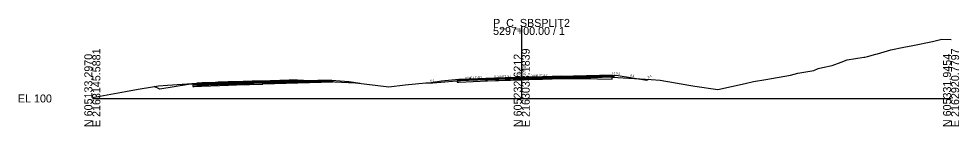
# Model space of a CAD drawing. Extents: x -26 to 1303, y -10 to 12033.
# Drawn here: x -25.7 to 302.8, y 8990.3 to 9027.8 of the extents above; entities that cross this region are included whole.
import ezdxf

# ---------------------------------------------------------------- set-up
doc = ezdxf.new("R2010")
doc.units = 0
for name, color, linetype in [('RD_GPK_XS_Cell', 7, 'Continuous'), ('RD_XS_Base', 7, 'Continuous'), ('RD_XS_ExGround', 7, 'Continuous'), ('RD_XS_ExPaveRet', 7, 'Continuous'), ('RD_XS_Greenside', 7, 'Continuous'), ('RD_XS_Pave', 7, 'Continuous'), ('RD_XS_PaveOvlay_CP', 7, 'Continuous'), ('RD_XS_TieSlope', 7, 'Continuous'), ('RD_XS_TX_Elev_EX', 7, 'Continuous'), ('RD_XS_TX_Elev_PR', 7, 'Continuous'), ('RD_XS_TX_ShdSlope', 7, 'Continuous'), ('RD_XS_TX_Slope', 7, 'Continuous')]:
    doc.layers.add(name, color=color, linetype=linetype)

msp = doc.modelspace()

# ---------------------------------------------------------------- linework, layer by layer
at = {"layer": 'RD_GPK_XS_Cell'}
for p, q in [((150, 9000), (150, 9025)), ((0, 9000), (150, 9000)), ((150, 9000), (300, 9000))]:
    msp.add_line(p, q, dxfattribs=at)
at = {"layer": 'RD_XS_Base'}
for p, q in [((47.57, 9005.2), (38.18, 9004.82)), ((50.32, 9005.27), (47.57, 9005.2)), ((59.57, 9005.51), (50.32, 9005.27)), ((59.57, 9005.51), (84.07, 9006.14)), ((59.57, 9005.01), (59.57, 9005.67)), ((59.57, 9005.67), (59.57, 9005.67)), ((59.57, 9005.67), (59.57, 9005.67)), ((59.57, 9005.67), (59.57, 9005.51)), ((84.07, 9005.64), (59.57, 9005.01)), ((59.57, 9005.51), (59.57, 9005.51)), ((59.57, 9005.01), (59.57, 9005.51)), ((59.57, 9005.51), (59.57, 9005.51)), ((59.57, 9005.51), (59.57, 9005.51)), ((83.57, 9006.13), (83.57, 9006.13)), ((83.57, 9006.13), (83.57, 9006.13)), ((83.57, 9006.13), (83.57, 9006.13)), ((83.57, 9005.63), (83.57, 9005.63)), ((83.57, 9005.63), (83.57, 9005.63)), ((84.07, 9006.14), (84.07, 9005.64)), ((84.07, 9006.11), (84.07, 9006.11)), ((128, 9006.25), (127.5, 9006.23)), ((127.5, 9006.23), (127.5, 9006.23)), ((127.5, 9006.23), (127.5, 9005.73)), ((127.5, 9005.73), (128, 9005.75)), ((138, 9006.65), (128, 9006.25)), ((128, 9006.25), (128, 9006.25)), ((128, 9005.75), (138, 9006.15)), ((128, 9005.75), (128, 9005.75)), ((136, 9006.57), (136, 9006.57)), ((136, 9006.07), (136, 9006.07)), ((150, 9006.99), (138, 9006.65)), ((138, 9006.15), (150, 9006.49)), ((150, 9006.99), (181.7, 9007.88)), ((182.2, 9007.39), (150, 9006.49)), ((150, 9006.49), (150, 9007.15)), ((150, 9007.15), (150, 9007.15)), ((150, 9007.15), (150, 9007.15)), ((150, 9007.15), (150, 9006.99)), ((150, 9006.99), (150, 9006.99)), ((150, 9006.49), (150, 9006.99)), ((150, 9006.99), (150, 9006.99)), ((150, 9006.99), (150, 9006.99)), ((150, 9006.49), (150, 9006.49)), ((162, 9007.33), (162, 9007.33)), ((162, 9007.33), (162, 9007.33)), ((162, 9006.83), (162, 9006.83)), ((162, 9006.83), (162, 9006.83)), ((181.7, 9007.88), (181.7, 9007.88)), ((182.2, 9007.89), (182.2, 9007.39)), ((182.2, 9007.86), (182.2, 9007.86)), ((35.17, 9004.7), (35.06, 9004.7)), ((35.06, 9004.7), (35.06, 9004.3)), ((35.06, 9004.3), (35.06, 9004.2)), ((35.06, 9004.2), (35.17, 9004.2)), ((35.56, 9004.72), (35.17, 9004.7)), ((35.17, 9004.2), (35.56, 9004.22)), ((38.18, 9004.82), (35.56, 9004.72)), ((35.56, 9004.22), (38.18, 9004.32)), ((38.18, 9004.32), (47.57, 9004.7)), ((47.57, 9004.7), (50.32, 9004.77)), ((50.32, 9004.77), (59.57, 9005.01)), ((59.57, 9005.01), (59.57, 9005.01))]:
    msp.add_line(p, q, dxfattribs=at)
at = {"layer": 'RD_XS_ExGround'}
msp.add_lwpolyline([(0, 9000.36), (8.97, 9002.02), (11.57, 9002.4), (15.95, 9003.2), (21.02, 9004.11), (23.12, 9004.47), (26.23, 9004.68), (36.51, 9005.35), (42.99, 9005.63), (44.96, 9005.69), (52.73, 9005.91), (55.29, 9005.98), (56.4, 9006.04), (68.75, 9006.37), (70.77, 9006.42), (71.71, 9006.45), (73.79, 9006.35), (74.65, 9006.3), (91.97, 9005.49), (94.99, 9005.14), (103.59, 9004.12), (109.3, 9004.72), (116.51, 9005.44), (116.93, 9005.45), (118.98, 9005.5), (130.01, 9006.34), (137.5, 9006.97), (144.26, 9007.18), (149.82, 9007.36), (151.67, 9007.42), (153.08, 9007.45), (155, 9007.49), (155.13, 9007.5), (157.28, 9007.55), (163.97, 9007.75), (171.13, 9007.67), (176.53, 9007.59), (181.57, 9007.48), (195.21, 9006.64), (198.35, 9006.45), (208.4, 9004.65), (209.09, 9004.53), (210.45, 9004.33), (218.53, 9003.1), (228.1, 9005.25), (230.98, 9005.94), (235.27, 9006.57), (243.85, 9008.16), (245.14, 9008.48), (246.47, 9008.79), (252.02, 9009.8), (253.62, 9010.46), (255.13, 9010.85), (258.48, 9011.54), (261.66, 9012.73), (263.65, 9013.51), (269.58, 9014.41), (269.75, 9014.42), (269.88, 9014.47), (270.83, 9014.71), (273.77, 9015.48), (274.26, 9015.63), (278.94, 9016.95), (283.51, 9017.96), (286.69, 9018.49), (293.54, 9019.87), (296.82, 9020.67), (300, 9020.62)], dxfattribs=at)
at = {"layer": 'RD_XS_ExPaveRet'}
for points in [[(70.77, 9006.42), (68.75, 9006.37), (62.08, 9006.19), (56.4, 9006.04), (55.85, 9006.01), (55.29, 9005.98), (54.01, 9005.95), (52.73, 9005.91), (47.42, 9005.76), (44.96, 9005.69), (43.98, 9005.66), (42.99, 9005.63), (38.38, 9005.43), (36.51, 9005.35), (36.51, 9005.35), (36.51, 9005.35), (36.51, 9004.84), (36.51, 9004.6), (36.51, 9004.6), (36.51, 9004.6), (38.38, 9004.68), (42.99, 9004.88), (43.98, 9004.91), (44.96, 9004.94), (47.42, 9005.01), (52.73, 9005.16), (54.01, 9005.2), (55.29, 9005.23), (55.85, 9005.26), (56.4, 9005.29), (62.08, 9005.44), (68.75, 9005.62), (70.77, 9005.67), (71.71, 9005.7), (71.71, 9006.04), (71.71, 9006.45), (70.77, 9006.42)], [(70.77, 9006.42), (68.75, 9006.37), (62.08, 9006.19), (56.4, 9006.04), (55.85, 9006.01), (55.29, 9005.98), (54.01, 9005.95), (52.73, 9005.91), (47.42, 9005.76), (44.96, 9005.69), (43.98, 9005.66), (42.99, 9005.63), (38.38, 9005.43), (36.51, 9005.35), (36.51, 9005.35), (36.51, 9004.84), (36.51, 9004.6), (36.51, 9004.6), (38.38, 9004.68), (42.99, 9004.88), (43.98, 9004.91), (44.96, 9004.94), (47.42, 9005.01), (52.73, 9005.16), (54.01, 9005.2), (55.29, 9005.23), (55.85, 9005.26), (56.4, 9005.29), (62.08, 9005.44), (68.75, 9005.62), (70.77, 9005.67), (71.71, 9005.7), (71.71, 9006.04), (71.71, 9006.45), (70.77, 9006.42)], [(181.57, 9007.48), (176.53, 9007.59), (171.13, 9007.67), (171.13, 9007.67), (163.97, 9007.75), (157.28, 9007.55), (157.28, 9007.55), (157.28, 9007.55), (155.13, 9007.5), (155, 9007.49), (153.08, 9007.45), (153.08, 9007.45), (153.08, 9007.45), (151.67, 9007.42), (151.67, 9007.42), (149.82, 9007.36), (149.82, 9007.36), (149.82, 9007.36), (144.26, 9007.18), (144.26, 9007.18), (137.5, 9006.97), (137.5, 9006.97), (137.5, 9006.97), (137.5, 9006.22), (137.5, 9006.22), (144.26, 9006.43), (144.26, 9006.43), (149.82, 9006.61), (149.82, 9006.61), (149.82, 9006.61), (151.67, 9006.67), (151.67, 9006.67), (153.08, 9006.7), (153.08, 9006.7), (153.08, 9006.7), (155, 9006.74), (155.13, 9006.75), (157.28, 9006.8), (157.28, 9006.8), (157.28, 9006.8), (163.97, 9007), (171.13, 9006.92), (171.13, 9006.92), (176.53, 9006.84), (181.57, 9006.73), (181.57, 9006.73), (181.57, 9006.73), (181.57, 9007.48), (181.57, 9007.48), (181.57, 9007.48), (181.57, 9007.48)], [(181.57, 9007.48), (176.53, 9007.59), (171.13, 9007.67), (163.97, 9007.75), (157.28, 9007.55), (155.13, 9007.5), (155, 9007.49), (153.08, 9007.45), (151.67, 9007.42), (149.82, 9007.36), (144.26, 9007.18), (137.5, 9006.97), (137.5, 9006.97), (137.5, 9006.22), (137.5, 9006.22), (144.26, 9006.43), (149.82, 9006.61), (151.67, 9006.67), (153.08, 9006.7), (155, 9006.74), (155.13, 9006.75), (157.28, 9006.8), (163.97, 9007), (171.13, 9006.92), (176.53, 9006.84), (181.57, 9006.73), (181.57, 9007.48)]]:
    msp.add_lwpolyline(points, dxfattribs=at)
at = {"layer": 'RD_XS_Greenside'}
for p, q in [((89.57, 9005.97), (93.53, 9005.31)), ((122, 9006.09), (118.36, 9005.48)), ((183.7, 9008.04), (193.7, 9006.37)), ((193.7, 9006.37), (194.36, 9006.69)), ((23.56, 9003.21), (21.6, 9004.19)), ((33.56, 9004.87), (23.56, 9003.21))]:
    msp.add_line(p, q, dxfattribs=at)
at = {"layer": 'RD_XS_Pave'}
for p, q in [((38.18, 9005.14), (35.56, 9005.03)), ((47.57, 9005.51), (38.18, 9005.14)), ((38.18, 9004.98), (47.57, 9005.36)), ((47.57, 9005.36), (38.18, 9004.98)), ((38.18, 9004.82), (47.57, 9005.2)), ((50.32, 9005.59), (47.57, 9005.51)), ((47.57, 9005.36), (50.32, 9005.43)), ((50.32, 9005.43), (47.57, 9005.36)), ((47.57, 9005.2), (50.32, 9005.27)), ((59.57, 9005.83), (50.32, 9005.59)), ((50.32, 9005.43), (59.57, 9005.67)), ((59.57, 9005.67), (50.32, 9005.43)), ((50.32, 9005.27), (59.57, 9005.51)), ((83.57, 9006.45), (59.57, 9005.83)), ((83.57, 9006.29), (59.57, 9005.67)), ((59.57, 9005.67), (83.57, 9006.29)), ((59.57, 9005.51), (83.57, 9006.13)), ((59.57, 9005.83), (59.57, 9005.83)), ((59.57, 9005.67), (59.57, 9005.67)), ((59.57, 9005.67), (59.57, 9005.67)), ((59.57, 9005.67), (59.57, 9005.51)), ((59.57, 9005.67), (59.57, 9005.67)), ((59.57, 9005.51), (59.57, 9005.67)), ((59.57, 9005.67), (59.57, 9005.67)), ((59.57, 9005.67), (59.57, 9005.67)), ((59.57, 9005.51), (59.57, 9005.51)), ((59.57, 9005.51), (59.57, 9005.51)), ((83.57, 9006.29), (83.57, 9006.45)), ((83.57, 9006.45), (83.57, 9006.45)), ((83.57, 9006.45), (83.57, 9006.45)), ((83.57, 9006.45), (83.57, 9006.45)), ((83.57, 9006.13), (83.57, 9006.29)), ((83.57, 9006.29), (83.57, 9006.29)), ((83.57, 9006.29), (83.57, 9006.29)), ((83.57, 9006.29), (83.57, 9006.29)), ((83.57, 9006.29), (83.57, 9006.29)), ((83.57, 9006.29), (83.57, 9006.29)), ((83.57, 9006.13), (83.57, 9006.13)), ((83.57, 9006.13), (83.57, 9006.13)), ((138, 9006.97), (128, 9006.57)), ((128, 9006.41), (138, 9006.81)), ((138, 9006.81), (128, 9006.41)), ((128, 9006.25), (138, 9006.65)), ((128, 9006.57), (128, 9006.57)), ((128, 9006.57), (128, 9006.41)), ((128, 9006.41), (128, 9006.41)), ((128, 9006.41), (128, 9006.25)), ((136, 9006.89), (136, 9006.89)), ((136, 9006.73), (136, 9006.73)), ((136, 9006.73), (136, 9006.73)), ((136, 9006.57), (136, 9006.57)), ((150, 9007.31), (138, 9006.97)), ((138, 9006.81), (150, 9007.15)), ((150, 9007.15), (138, 9006.81)), ((138, 9006.65), (150, 9006.99)), ((181.7, 9008.2), (150, 9007.31)), ((181.7, 9008.04), (150, 9007.15)), ((150, 9007.15), (181.7, 9008.04)), ((150, 9006.99), (182.2, 9007.89)), ((150, 9007.31), (150, 9007.31)), ((150, 9007.15), (150, 9007.15)), ((150, 9007.15), (150, 9007.15)), ((150, 9007.15), (150, 9006.99)), ((150, 9007.15), (150, 9007.15)), ((150, 9006.99), (150, 9007.15)), ((150, 9007.15), (150, 9007.15)), ((150, 9007.15), (150, 9007.15)), ((150, 9006.99), (150, 9006.99)), ((150, 9006.99), (150, 9006.99)), ((162, 9007.64), (162, 9007.64)), ((162, 9007.64), (162, 9007.64)), ((162, 9007.49), (162, 9007.49)), ((162, 9007.49), (162, 9007.49)), ((162, 9007.49), (162, 9007.49)), ((162, 9007.49), (162, 9007.49)), ((162, 9007.33), (162, 9007.33)), ((162, 9007.33), (162, 9007.33)), ((181.7, 9008.04), (181.7, 9008.2)), ((181.7, 9008.2), (181.7, 9008.2)), ((181.7, 9007.88), (181.7, 9008.04)), ((181.7, 9008.04), (181.7, 9008.04)), ((35.56, 9005.03), (35.56, 9004.91)), ((35.56, 9004.88), (38.18, 9004.98)), ((38.18, 9004.98), (35.56, 9004.88)), ((35.56, 9004.91), (35.56, 9004.88)), ((35.56, 9004.88), (35.56, 9004.75)), ((35.56, 9004.72), (38.18, 9004.82)), ((35.56, 9004.75), (35.56, 9004.72))]:
    msp.add_line(p, q, dxfattribs=at)
at = {"layer": 'RD_XS_PaveOvlay_CP'}
for p, q in [((38.18, 9005.14), (35.56, 9005.03)), ((47.57, 9005.51), (38.18, 9005.14)), ((50.32, 9005.59), (47.57, 9005.51)), ((59.57, 9005.83), (50.32, 9005.59)), ((83.57, 9006.45), (59.57, 9005.83)), ((59.57, 9005.83), (59.57, 9005.83)), ((83.57, 9006.45), (83.57, 9006.45)), ((83.57, 9006.45), (83.57, 9006.45)), ((138, 9006.97), (128, 9006.57)), ((136, 9006.89), (136, 9006.89)), ((150, 9007.31), (138, 9006.97)), ((181.7, 9008.2), (150, 9007.31)), ((150, 9007.31), (150, 9007.31)), ((162, 9007.64), (162, 9007.64)), ((162, 9007.64), (162, 9007.64))]:
    msp.add_line(p, q, dxfattribs=at)
at = {"layer": 'RD_XS_TieSlope'}
for p, q in [((83.57, 9006.45), (89.57, 9005.97)), ((128, 9006.57), (122, 9006.09)), ((181.7, 9008.2), (183.7, 9008.04)), ((35.56, 9005.03), (33.56, 9004.87))]:
    msp.add_line(p, q, dxfattribs=at)

# ---------------------------------------------------------------- texts
at = {"layer": 'RD_GPK_XS_Cell'}
for s, p in [('5297+00.00 / 1', (140, 9022.2)), ('P_C_SBSPLIT2', (140, 9025)), ('EL 100', (-26, 8998.6))]:
    msp.add_text(s, height=2.8, dxfattribs=at).set_placement(p)
for s, p in [('N 605133.2970', (0, 8990)), ('E 2163145.5881', (2.8, 8990)), ('N 605232.6212', (150, 8990)), ('E 2163033.1839', (152.8, 8990)), ('N 605331.9454', (300, 8990)), ('E 2162920.7797', (302.8, 8990))]:
    msp.add_text(s, height=2.8, rotation=90, dxfattribs=at).set_placement(p)
at = {"layer": 'RD_XS_TX_Elev_EX'}
msp.add_text('107.36', height=0.6, rotation=90, dxfattribs=at).set_placement((149.49, 9008.28))
at = {"layer": 'RD_XS_TX_Elev_PR'}
msp.add_text('107.31', height=1, rotation=90, dxfattribs=at).set_placement((151.33, 9007.85))
at = {"layer": 'RD_XS_TX_ShdSlope'}
msp.add_text('12.5:1', height=0.75, rotation=355.4261, dxfattribs=at).set_placement((181.5, 9008.53))
at = {"layer": 'RD_XS_TX_Slope'}
for s, rotation, p in [('0.030 FT./FT.', 1.7184, (153.16, 9007.57)), ('6:1', 350.5358, (187.84, 9007.72)), ('6:1', 9.4623, (118.12, 9005.75)), ('0.040 FT./FT.', 2.2906, (130.15, 9006.78)), ('0.030 FT./FT.', 1.7184, (140.42, 9007.21)), ('2:1', 26.5651, (194.22, 9007.04))]:
    msp.add_text(s, height=0.75, rotation=rotation, dxfattribs=at).set_placement(p)

doc.saveas('drawing.dxf')
